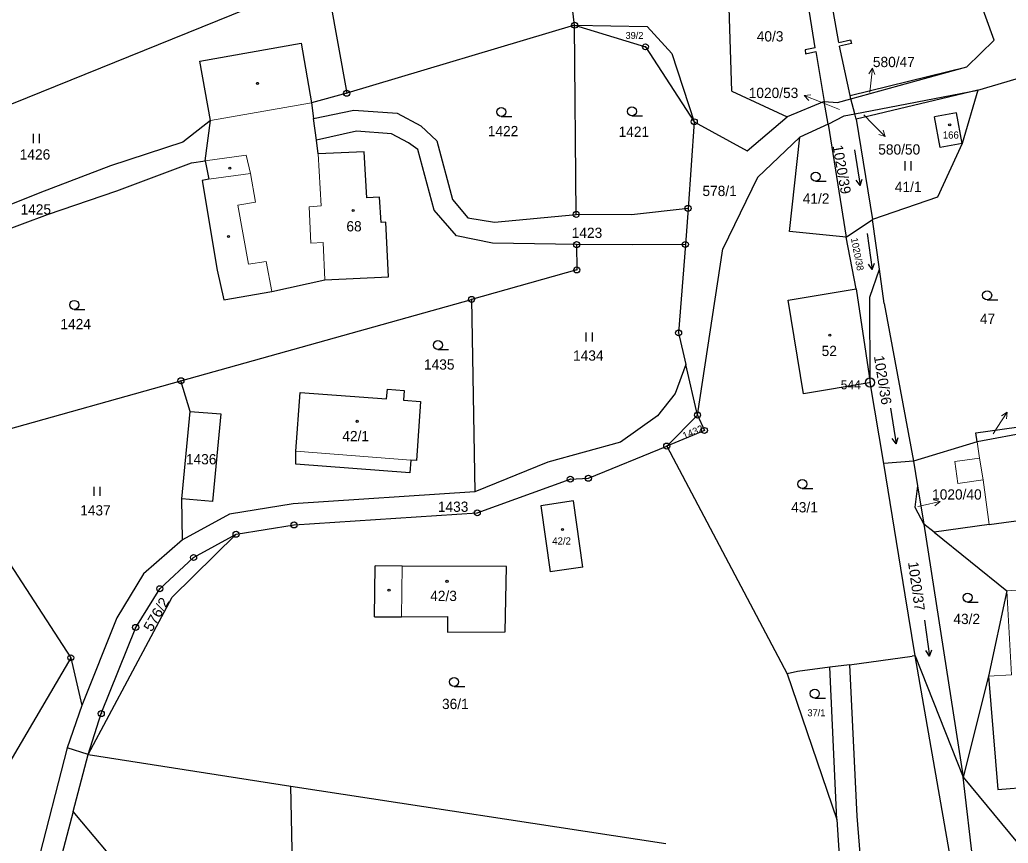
# Model space of a CAD drawing. Extents: x -601131 to -597152, y -1058536 to -1055911.
# Drawn here: x -599584.4 to -599420.5, y -1057414.9 to -1057278.4 of the extents above; entities that cross this region are included whole.
import ezdxf
from ezdxf.enums import TextEntityAlignment as Align

# ---------------------------------------------------------------- set-up
doc = ezdxf.new("R2010")
doc.units = 0
doc.header["$LTSCALE"] = 0.68
for name, color, linetype, lineweight in [('1', 7, 'Continuous', 25), ('3', 7, 'Continuous', 25), ('4', 7, 'Continuous', 13), ('5', 7, 'Continuous', 25), ('7', 7, 'Continuous', 13), ('8', 7, 'Continuous', 25)]:
    doc.layers.add(name, color=color, linetype=linetype, lineweight=lineweight)
doc.layers.add('2', color=7, linetype='Continuous')

msp = doc.modelspace()

# ---------------------------------------------------------------- linework, layer by layer
at = {"layer": '1'}
for p, q in [((-599492.41, -1057279.26), (-599496.24, -1057248.99)), ((-599452.51, -1057283), (-599457.48, -1057251.31)), ((-599448.59, -1057282.13), (-599454.14, -1057251.12)), ((-599422.85, -1057281.74), (-599428.69, -1057265.15)), ((-599533.67, -1057271.24), (-599655.03, -1057320.42)), ((-599533.67, -1057271.24), (-599530.2, -1057290.54)), ((-599466.34, -1057290.2), (-599466.89, -1057273.22)), ((-599492.41, -1057279.26), (-599530.2, -1057290.54)), ((-599492.41, -1057279.26), (-599480.38, -1057279.48)), ((-599492.41, -1057279.26), (-599480.65, -1057282.84)), ((-599492.14, -1057310.63), (-599492.41, -1057279.26)), ((-599480.38, -1057279.48), (-599476.29, -1057283.95)), ((-599554.56, -1057285.24), (-599537.77, -1057282.26)), ((-599537.77, -1057282.26), (-599536.01, -1057292.14)), ((-599480.65, -1057282.84), (-599472.56, -1057295.27)), ((-599448.59, -1057282.13), (-599446.63, -1057281.7)), ((-599446.48, -1057282.32), (-599448.47, -1057282.76)), ((-599446.73, -1057290.92), (-599448.47, -1057282.76)), ((-599446.63, -1057281.7), (-599446.48, -1057282.32)), ((-599427.36, -1057286.17), (-599422.85, -1057281.74)), ((-599476.29, -1057283.95), (-599472.56, -1057295.27)), ((-599452.51, -1057283), (-599454.18, -1057283.37)), ((-599454.18, -1057283.37), (-599454.13, -1057284.02)), ((-599454.13, -1057284.02), (-599452.39, -1057283.63)), ((-599452.39, -1057283.63), (-599451.02, -1057291.89)), ((-599552.77, -1057295.08), (-599554.56, -1057285.24)), ((-599446.73, -1057290.92), (-599427.36, -1057286.17)), ((-599446.59, -1057291.48), (-599427.36, -1057286.17)), ((-599425.53, -1057290.01), (-599413.41, -1057286.42)), ((-599530.2, -1057290.54), (-599536.01, -1057292.14)), ((-599466.34, -1057290.2), (-599457.17, -1057294.45)), ((-599446.59, -1057291.48), (-599446.73, -1057290.92)), ((-599445.96, -1057293.94), (-599425.53, -1057290.01)), ((-599425.53, -1057290.01), (-599445.73, -1057294.82)), ((-599425.53, -1057290.01), (-599428.11, -1057298.85)), ((-599536.01, -1057292.14), (-599535.68, -1057294.72)), ((-599451.02, -1057291.89), (-599457.17, -1057294.45)), ((-599451.02, -1057291.89), (-599448.79, -1057292.09)), ((-599450.38, -1057295.69), (-599451.02, -1057291.89)), ((-599448.79, -1057292.09), (-599446.59, -1057291.48)), ((-599445.96, -1057293.94), (-599446.59, -1057291.48)), ((-599535.68, -1057294.72), (-599529, -1057293.34)), ((-599529, -1057293.34), (-599521.84, -1057293.86)), ((-599521.84, -1057293.86), (-599517.91, -1057295.92)), ((-599463.81, -1057300.06), (-599457.17, -1057294.45)), ((-599450.38, -1057295.69), (-599447.7, -1057294.28)), ((-599447.7, -1057294.28), (-599445.96, -1057293.94)), ((-599445.73, -1057294.82), (-599445.96, -1057293.94)), ((-599429.07, -1057293.76), (-599432.75, -1057294.45)), ((-599431.79, -1057299.51), (-599432.75, -1057294.45)), ((-599428.11, -1057298.85), (-599429.07, -1057293.76)), ((-599552.77, -1057295.08), (-599557.36, -1057298.63)), ((-599553.64, -1057301.75), (-599552.77, -1057295.08)), ((-599535.22, -1057298.3), (-599535.68, -1057294.72)), ((-599517.91, -1057295.92), (-599515.24, -1057298.44)), ((-599472.56, -1057295.27), (-599473.6, -1057309.62)), ((-599472.56, -1057295.27), (-599463.81, -1057300.06)), ((-599450.38, -1057295.69), (-599455.08, -1057297.81)), ((-599450.38, -1057295.69), (-599447.39, -1057314.38)), ((-599445.73, -1057294.82), (-599442.98, -1057311.49)), ((-599528.55, -1057296.81), (-599535.22, -1057298.3)), ((-599522.75, -1057297.24), (-599528.55, -1057296.81)), ((-599519.95, -1057298.76), (-599522.75, -1057297.24)), ((-599557.36, -1057298.63), (-599569.37, -1057302.56)), ((-599534.92, -1057300.58), (-599535.22, -1057298.3)), ((-599518.42, -1057299.89), (-599519.95, -1057298.76)), ((-599515.24, -1057298.44), (-599512.64, -1057308.17)), ((-599462.09, -1057304.48), (-599455.08, -1057297.81)), ((-599456.78, -1057313.48), (-599455.08, -1057297.81)), ((-599428.11, -1057298.85), (-599432.25, -1057307.76)), ((-599428.11, -1057298.85), (-599431.79, -1057299.51)), ((-599527.3, -1057300.24), (-599534.92, -1057300.58)), ((-599526.87, -1057307.89), (-599527.3, -1057300.24)), ((-599515.68, -1057309.9), (-599518.42, -1057299.89)), ((-599569.37, -1057302.56), (-599581.09, -1057307.07)), ((-599568.34, -1057306.74), (-599555.93, -1057302.1)), ((-599555.93, -1057302.1), (-599553.64, -1057301.75)), ((-599553.64, -1057301.75), (-599553.04, -1057304.79)), ((-599553.04, -1057304.79), (-599554.18, -1057305.02)), ((-599554.18, -1057305.02), (-599551.67, -1057319.89)), ((-599462.09, -1057304.48), (-599467.85, -1057316.33)), ((-599581.09, -1057307.07), (-599593.17, -1057311.84)), ((-599579.79, -1057310.66), (-599568.34, -1057306.74)), ((-599524.73, -1057307.77), (-599526.87, -1057307.89)), ((-599524.5, -1057311.98), (-599524.73, -1057307.77)), ((-599512.64, -1057308.17), (-599510.12, -1057311.19)), ((-599432.25, -1057307.76), (-599442.98, -1057311.49)), ((-599591.79, -1057315.05), (-599579.79, -1057310.66)), ((-599512.01, -1057314.2), (-599515.68, -1057309.9)), ((-599505.68, -1057311.91), (-599492.14, -1057310.63)), ((-599482.98, -1057310.67), (-599492.14, -1057310.63)), ((-599473.6, -1057309.62), (-599482.98, -1057310.67)), ((-599473.6, -1057309.62), (-599474.03, -1057315.61)), ((-599523.7, -1057311.93), (-599524.5, -1057311.98)), ((-599523.26, -1057320.96), (-599523.7, -1057311.93)), ((-599510.12, -1057311.19), (-599505.68, -1057311.91)), ((-599447.39, -1057314.38), (-599442.98, -1057311.49)), ((-599441.85, -1057319.7), (-599442.98, -1057311.49)), ((-599447.39, -1057314.38), (-599456.78, -1057313.48)), ((-599506.01, -1057315.39), (-599512.01, -1057314.2)), ((-599492.08, -1057315.63), (-599506.01, -1057315.39)), ((-599482.76, -1057315.67), (-599492.08, -1057315.63)), ((-599492.08, -1057315.63), (-599492.04, -1057319.83)), ((-599474.03, -1057315.61), (-599482.76, -1057315.67)), ((-599474.03, -1057315.61), (-599475.16, -1057330.26)), ((-599445.72, -1057322.97), (-599447.39, -1057314.38)), ((-599472.02, -1057343.89), (-599467.85, -1057316.33)), ((-599551.67, -1057319.89), (-599550.59, -1057324.81)), ((-599492.04, -1057319.83), (-599509.5, -1057324.72)), ((-599443.43, -1057324.34), (-599441.85, -1057319.7)), ((-599441.06, -1057325.39), (-599441.85, -1057319.7)), ((-599542.62, -1057323.42), (-599533.81, -1057321.47)), ((-599533.81, -1057321.47), (-599523.26, -1057320.96)), ((-599550.59, -1057324.81), (-599542.62, -1057323.42)), ((-599456.99, -1057324.85), (-599445.72, -1057322.97)), ((-599445.72, -1057322.97), (-599443.39, -1057338.51)), ((-599557.68, -1057338.2), (-599509.5, -1057324.72)), ((-599509.5, -1057324.72), (-599508.95, -1057356.62)), ((-599454.46, -1057340.37), (-599456.99, -1057324.85)), ((-599443.39, -1057338.51), (-599443.43, -1057324.34)), ((-599441.06, -1057325.39), (-599436.21, -1057351.52)), ((-599475.16, -1057330.26), (-599473.95, -1057335.51)), ((-599473.95, -1057335.51), (-599475.75, -1057340.33)), ((-599472.02, -1057343.89), (-599473.95, -1057335.51)), ((-599598.4, -1057349.59), (-599557.68, -1057338.2)), ((-599556.17, -1057343.31), (-599557.68, -1057338.2)), ((-599443.56, -1057338.54), (-599454.46, -1057340.37)), ((-599443.39, -1057338.51), (-599443.56, -1057338.54)), ((-599441.15, -1057351.91), (-599443.39, -1057338.51)), ((-599538.63, -1057349.88), (-599537.94, -1057340.12)), ((-599537.94, -1057340.12), (-599523.57, -1057341.2)), ((-599523.57, -1057341.2), (-599523.44, -1057339.61)), ((-599523.44, -1057339.61), (-599520.65, -1057339.82)), ((-599520.65, -1057339.82), (-599520.75, -1057341.41)), ((-599475.75, -1057340.33), (-599478.67, -1057344.04)), ((-599520.75, -1057341.41), (-599517.95, -1057341.64)), ((-599517.95, -1057341.64), (-599518.61, -1057351.42)), ((-599557.53, -1057357.79), (-599556.17, -1057343.31)), ((-599556.17, -1057343.31), (-599551.09, -1057343.7)), ((-599551.09, -1057343.7), (-599552.47, -1057358.19)), ((-599478.67, -1057344.04), (-599484.82, -1057348.37)), ((-599477.13, -1057349.03), (-599472.02, -1057343.89)), ((-599472.02, -1057343.89), (-599470.88, -1057346.44)), ((-599425.85, -1057346.84), (-599409.99, -1057344.56)), ((-599470.88, -1057346.44), (-599477.13, -1057349.03)), ((-599425.64, -1057348.31), (-599425.85, -1057346.84)), ((-599409.88, -1057345.35), (-599425.64, -1057348.31)), ((-599484.82, -1057348.37), (-599496.86, -1057351.67)), ((-599425.64, -1057348.31), (-599436.21, -1057351.52)), ((-599598.4, -1057349.59), (-599575.95, -1057384.13)), ((-599538.61, -1057352.05), (-599538.63, -1057349.88)), ((-599490.11, -1057354.37), (-599477.13, -1057349.03)), ((-599477.13, -1057349.03), (-599457.16, -1057386.76)), ((-599519.54, -1057351.38), (-599519.7, -1057353.46)), ((-599518.61, -1057351.42), (-599519.54, -1057351.38)), ((-599496.86, -1057351.67), (-599508.95, -1057356.62)), ((-599436.21, -1057351.52), (-599441.15, -1057351.91)), ((-599436.21, -1057351.52), (-599435.55, -1057355.6)), ((-599519.7, -1057353.46), (-599538.61, -1057352.05)), ((-599437.59, -1057373.7), (-599441.15, -1057351.91)), ((-599508.55, -1057360.1), (-599493.12, -1057354.51)), ((-599493.12, -1057354.51), (-599490.11, -1057354.37)), ((-599508.95, -1057356.62), (-599539.06, -1057358.6)), ((-599435.55, -1057355.6), (-599435.98, -1057359.17)), ((-599435.55, -1057355.6), (-599434.51, -1057361.95)), ((-599552.47, -1057358.19), (-599557.53, -1057357.79)), ((-599557.45, -1057364.56), (-599557.53, -1057357.79)), ((-599492.6, -1057358.12), (-599497.98, -1057358.91)), ((-599491.02, -1057369.11), (-599492.6, -1057358.12)), ((-599539.06, -1057358.6), (-599549.61, -1057360.32)), ((-599497.98, -1057358.91), (-599496.44, -1057369.85)), ((-599435.98, -1057359.17), (-599434.51, -1057361.95)), ((-599423.64, -1057362.04), (-599397.5, -1057358.39)), ((-599549.61, -1057360.32), (-599557.45, -1057364.56)), ((-599538.92, -1057362.1), (-599508.55, -1057360.1)), ((-599548.54, -1057363.65), (-599538.92, -1057362.1)), ((-599432.8, -1057363.32), (-599434.51, -1057361.95)), ((-599434.51, -1057361.95), (-599427.99, -1057403.92)), ((-599423.64, -1057362.04), (-599432.8, -1057363.32)), ((-599557.45, -1057364.56), (-599563.87, -1057370.18)), ((-599559.12, -1057374.07), (-599548.54, -1057363.65)), ((-599555.58, -1057367.5), (-599548.54, -1057363.65)), ((-599432.8, -1057363.32), (-599420.72, -1057373.02)), ((-599561.19, -1057372.67), (-599555.58, -1057367.5)), ((-599525.6, -1057377.33), (-599525.47, -1057368.9)), ((-599520.98, -1057368.91), (-599525.47, -1057368.9)), ((-599503.67, -1057368.97), (-599520.98, -1057368.91)), ((-599503.9, -1057379.84), (-599503.67, -1057368.97)), ((-599491.02, -1057369.11), (-599496.44, -1057369.85)), ((-599563.87, -1057370.18), (-599568.3, -1057377.48)), ((-599565.19, -1057379.09), (-599561.19, -1057372.67)), ((-599420.72, -1057373.02), (-599423.75, -1057387.17)), ((-599573.06, -1057400.18), (-599559.12, -1057374.07)), ((-599435.94, -1057383.82), (-599437.59, -1057373.7)), ((-599568.3, -1057377.48), (-599574.13, -1057392.06)), ((-599525.6, -1057377.33), (-599521.1, -1057377.31)), ((-599521.1, -1057377.31), (-599513.5, -1057377.29)), ((-599513.5, -1057377.29), (-599513.49, -1057379.88)), ((-599570.89, -1057393.38), (-599565.19, -1057379.09)), ((-599513.49, -1057379.88), (-599503.9, -1057379.84)), ((-599575.95, -1057384.13), (-599608.22, -1057439.01)), ((-599575.95, -1057384.13), (-599574.13, -1057392.06)), ((-599446.83, -1057385.27), (-599436.42, -1057383.88)), ((-599435.94, -1057383.82), (-599436.42, -1057383.88)), ((-599435.94, -1057383.82), (-599427.99, -1057403.92)), ((-599429.13, -1057422.65), (-599435.94, -1057383.82)), ((-599450.07, -1057385.7), (-599455.47, -1057386.42)), ((-599446.83, -1057385.27), (-599450.07, -1057385.7)), ((-599448.9, -1057410.94), (-599450.07, -1057385.7)), ((-599446.83, -1057385.27), (-599445.63, -1057410.37)), ((-599455.47, -1057386.42), (-599457.16, -1057386.76)), ((-599457.16, -1057386.76), (-599448.9, -1057410.94)), ((-599423.75, -1057387.17), (-599427.99, -1057403.92)), ((-599423.75, -1057387.17), (-599422.24, -1057405.98)), ((-599574.13, -1057392.06), (-599576.56, -1057399.07)), ((-599573.06, -1057400.18), (-599570.89, -1057393.38)), ((-599576.56, -1057399.07), (-599582.83, -1057423.44)), ((-599573.06, -1057400.18), (-599576.56, -1057399.07)), ((-599575.56, -1057409.62), (-599573.06, -1057400.18)), ((-599573.06, -1057400.18), (-599539.45, -1057405.43)), ((-599427.99, -1057403.92), (-599418.95, -1057414.8)), ((-599425.81, -1057422.29), (-599427.99, -1057403.92)), ((-599539.45, -1057405.43), (-599477.25, -1057414.93)), ((-599538.83, -1057434.23), (-599539.45, -1057405.43)), ((-599422.24, -1057405.98), (-599409.22, -1057404.94)), ((-599575.56, -1057409.62), (-599579.52, -1057424.57)), ((-599574.11, -1057411.33), (-599575.56, -1057409.62)), ((-599445.63, -1057410.37), (-599444.9, -1057418.96)), ((-599553.62, -1057435.58), (-599574.11, -1057411.33)), ((-599448.9, -1057410.94), (-599448.41, -1057419.24))]:
    msp.add_line(p, q, dxfattribs=at)
at = {"layer": '3'}
for p, q in [((-599504.573, -1057294.38), (-599502.823, -1057294.38)), ((-599482.903, -1057294.3), (-599481.153, -1057294.3)), ((-599582.151, -1057298.79), (-599582.151, -1057297.29)), ((-599581.15, -1057298.79), (-599581.15, -1057297.29)), ((-599437.571, -1057303.32), (-599437.571, -1057301.82)), ((-599436.57, -1057303.32), (-599436.57, -1057301.82)), ((-599452.433, -1057305.11), (-599450.683, -1057305.11)), ((-599445.046, -1057305.831), (-599445.695, -1057304.945)), ((-599443.059, -1057319.749), (-599443.691, -1057318.851)), ((-599423.993, -1057324.79), (-599422.243, -1057324.79)), ((-599575.383, -1057326.37), (-599573.633, -1057326.37)), ((-599490.461, -1057331.69), (-599490.461, -1057330.19)), ((-599489.46, -1057331.69), (-599489.46, -1057330.19)), ((-599515.073, -1057333.04), (-599513.323, -1057333.04)), ((-599439.106, -1057348.651), (-599439.755, -1057347.765)), ((-599572.061, -1057357.3), (-599572.061, -1057355.8)), ((-599571.06, -1057357.3), (-599571.06, -1057355.8)), ((-599454.643, -1057356.07), (-599452.893, -1057356.07)), ((-599427.243, -1057374.89), (-599425.493, -1057374.89)), ((-599433.549, -1057383.839), (-599434.181, -1057382.941)), ((-599512.383, -1057388.87), (-599510.633, -1057388.87)), ((-599452.573, -1057390.81), (-599450.823, -1057390.81))]:
    msp.add_line(p, q, dxfattribs=at)
for points in [[(-599445.985, -1057299.905), (-599445.046, -1057305.831), (-599444.704, -1057304.788)], [(-599443.894, -1057313.807), (-599443.059, -1057319.749), (-599442.698, -1057318.712)], [(-599440.045, -1057342.725), (-599439.106, -1057348.651), (-599438.764, -1057347.608)], [(-599434.384, -1057377.897), (-599433.549, -1057383.839), (-599433.188, -1057382.802)]]:
    msp.add_lwpolyline(points, dxfattribs=at)
for centre in [(-599482.9029, -1057293.5498), (-599504.5729, -1057293.6298), (-599452.4329, -1057304.3598), (-599423.9929, -1057324.0398), (-599575.3829, -1057325.6198), (-599515.0729, -1057332.2898), (-599454.6429, -1057355.3198), (-599427.2429, -1057374.1398), (-599512.3829, -1057388.1198), (-599452.5729, -1057390.0598)]:
    msp.add_circle(centre, 0.75, dxfattribs=at)
at = {"layer": '4'}
for p, q in [((-599536.01, -1057292.14), (-599552.77, -1057295.08)), ((-599553.64, -1057301.75), (-599546.87, -1057300.79)), ((-599546.87, -1057300.79), (-599546.16, -1057303.85)), ((-599534.44, -1057309.22), (-599534.92, -1057300.58)), ((-599546.16, -1057303.85), (-599553.04, -1057304.79)), ((-599546.16, -1057303.85), (-599545.32, -1057308.61)), ((-599545.32, -1057308.61), (-599548.27, -1057309.12)), ((-599548.27, -1057309.12), (-599546.46, -1057318.89)), ((-599536.43, -1057309.38), (-599534.44, -1057309.22)), ((-599536.15, -1057315.38), (-599536.43, -1057309.38)), ((-599534.11, -1057315.28), (-599536.15, -1057315.38)), ((-599533.81, -1057321.47), (-599534.11, -1057315.28)), ((-599546.46, -1057318.89), (-599543.53, -1057318.44)), ((-599543.53, -1057318.44), (-599542.62, -1057323.42)), ((-599425.64, -1057348.31), (-599425.26, -1057351.03)), ((-599538.63, -1057349.88), (-599519.54, -1057351.38)), ((-599425.26, -1057351.03), (-599429.38, -1057351.61)), ((-599429.38, -1057351.61), (-599428.87, -1057355.23)), ((-599424.65, -1057354.65), (-599425.26, -1057351.03)), ((-599428.87, -1057355.23), (-599424.65, -1057354.65)), ((-599424.65, -1057354.65), (-599423.64, -1057362.04)), ((-599520.98, -1057368.91), (-599521.1, -1057377.31)), ((-599420.72, -1057373.02), (-599411.3, -1057372.3)), ((-599420.72, -1057373.02), (-599419.97, -1057386.97)), ((-599419.97, -1057386.97), (-599423.75, -1057387.17))]:
    msp.add_line(p, q, dxfattribs=at)
at = {"layer": '5'}
for centre in [(-599544.9768, -1057288.9092), (-599430.2068, -1057295.7892), (-599549.5868, -1057302.9592), (-599529.1268, -1057309.9792), (-599549.7868, -1057314.2992), (-599450.0668, -1057330.6292), (-599528.4468, -1057344.9192), (-599494.4068, -1057362.8492), (-599513.5568, -1057371.4592), (-599523.1768, -1057372.9292)]:
    msp.add_circle(centre, 0.175, dxfattribs=at)
at = {"layer": '7'}
for p, q in [((-599443.016, -1057286.365), (-599443.619, -1057287.309)), ((-599454.322, -1057290.935), (-599453.566, -1057291.761)), ((-599440.898, -1057297.712), (-599441.252, -1057296.65)), ((-599420.676, -1057343.423), (-599421.641, -1057343.99)), ((-599431.796, -1057358.195), (-599432.884, -1057357.932))]:
    msp.add_line(p, q, dxfattribs=at)
for points in [[(-599443.44, -1057290.39), (-599443.33, -1057289.35), (-599443.016, -1057286.365), (-599442.623, -1057287.414)], [(-599448.47, -1057293.21), (-599451.52, -1057292.01), (-599454.322, -1057290.935), (-599453.207, -1057290.826)], [(-599444.46, -1057294.13), (-599443.02, -1057295.59), (-599440.898, -1057297.712), (-599441.96, -1057297.358)], [(-599422.99, -1057346.99), (-599422.31, -1057345.94), (-599420.676, -1057343.423), (-599420.801, -1057344.536)], [(-599435.47, -1057359.04), (-599434.72, -1057358.87), (-599431.796, -1057358.195), (-599432.659, -1057358.908)]]:
    msp.add_lwpolyline(points, dxfattribs=at)
at = {"layer": '8'}
for centre, radius in [((-599492.41, -1057279.2599), 0.5), ((-599492.41, -1057279.2599), 0.0303), ((-599480.65, -1057282.8399), 0.5), ((-599480.65, -1057282.8399), 0.0303), ((-599530.2, -1057290.5399), 0.5), ((-599530.2, -1057290.5399), 0.0303), ((-599472.56, -1057295.2699), 0.5), ((-599472.56, -1057295.2699), 0.0303), ((-599473.6, -1057309.6199), 0.5), ((-599492.14, -1057310.6299), 0.5), ((-599492.14, -1057310.6299), 0.0303), ((-599473.6, -1057309.6199), 0.0303), ((-599492.08, -1057315.6299), 0.5), ((-599492.08, -1057315.6299), 0.0303), ((-599474.03, -1057315.6099), 0.5), ((-599474.03, -1057315.6099), 0.0303), ((-599492.04, -1057319.8299), 0.5), ((-599492.04, -1057319.8299), 0.0303), ((-599509.5, -1057324.7199), 0.5), ((-599509.5, -1057324.7199), 0.0303), ((-599475.16, -1057330.2599), 0.5), ((-599475.16, -1057330.2599), 0.0303), ((-599557.68, -1057338.1999), 0.5), ((-599557.68, -1057338.1999), 0.0303), ((-599443.43, -1057338.4898), 0.75), ((-599443.43, -1057338.4898), 0.03), ((-599472.02, -1057343.8899), 0.5), ((-599472.02, -1057343.8899), 0.0303), ((-599470.88, -1057346.4399), 0.5), ((-599470.88, -1057346.4399), 0.0303), ((-599477.13, -1057349.0299), 0.5), ((-599477.13, -1057349.0299), 0.0303), ((-599493.12, -1057354.5099), 0.5), ((-599493.12, -1057354.5099), 0.0303), ((-599490.11, -1057354.3699), 0.5), ((-599490.11, -1057354.3699), 0.0303), ((-599508.55, -1057360.0999), 0.5), ((-599538.92, -1057362.0999), 0.5), ((-599508.55, -1057360.0999), 0.0303), ((-599548.54, -1057363.6499), 0.5), ((-599538.92, -1057362.0999), 0.0303), ((-599548.54, -1057363.6499), 0.0303), ((-599555.58, -1057367.4999), 0.5), ((-599555.58, -1057367.4999), 0.0303), ((-599561.19, -1057372.6699), 0.5), ((-599561.19, -1057372.6699), 0.0303), ((-599565.19, -1057379.0899), 0.5), ((-599565.19, -1057379.0899), 0.0303), ((-599575.95, -1057384.1299), 0.5), ((-599575.95, -1057384.1299), 0.0303), ((-599570.89, -1057393.3799), 0.5), ((-599570.89, -1057393.3799), 0.0303)]:
    msp.add_circle(centre, radius, dxfattribs=at)

# ---------------------------------------------------------------- texts
at = {"layer": '2'}
for s, height, p in [('39/2', 1.14, (-599483.96, -1057281.525)), ('40/3', 1.7, (-599462.2, -1057281.955)), ('580/47', 1.7, (-599442.94, -1057286.205)), ('166', 1.19, (-599431.35, -1057298.057)), ('580/50', 1.7, (-599442.05, -1057300.705)), ('578/1', 1.7, (-599471.2, -1057307.584)), ('41/1', 1.7, (-599439.3, -1057306.905)), ('41/2', 1.7, (-599454.57, -1057308.844)), ('47', 1.7, (-599425.19, -1057328.785)), ('52', 1.7, (-599451.44, -1057334.104)), ('1020/40', 1.7, (-599433.12, -1057357.895)), ('43/1', 1.7, (-599456.49, -1057360.025)), ('42/2', 1.19, (-599496.11, -1057365.347)), ('42/3', 1.7, (-599516.35, -1057374.715)), ('43/2', 1.7, (-599429.59, -1057378.535)), ('36/1', 1.7, (-599514.39, -1057392.625)), ('37/1', 1.14, (-599453.79, -1057393.815))]:
    msp.add_text(s, height=height, dxfattribs=at).set_placement(p)
msp.add_text('1020/53', height=1.7, dxfattribs=at).set_placement((-599455.31, -1057291.334), align=Align.RIGHT)
for s, p in [('1422', (-599504.27, -1057297.662)), ('1421', (-599482.58, -1057297.772)), ('1426', (-599581.88, -1057301.532)), ('1425', (-599581.75, -1057310.642)), ('68', (-599528.979, -1057313.442)), ('1423', (-599490.35, -1057314.522)), ('1424', (-599575.14, -1057329.652)), ('1434', (-599490.13, -1057334.872)), ('1435', (-599514.85, -1057336.352)), ('42/1', (-599528.709, -1057348.222)), ('1436', (-599554.33, -1057352.062)), ('1433', (-599512.55, -1057359.932)), ('1437', (-599571.86, -1057360.532))]:
    msp.add_text(s, height=1.7, dxfattribs=at).set_placement(p, align=Align.CENTER)
for s, height, rotation, p in [('1020/39', 1.7, 280, (-599449.638, -1057299.273)), ('1020/38', 1.14, 281, (-599446.589, -1057314.624)), ('1020/36', 1.7, 279, (-599442.779, -1057334.156)), ('1020/37', 1.7, 278, (-599437.12, -1057368.309))]:
    msp.add_text(s, height=height, rotation=rotation, dxfattribs=at).set_placement(p)
at = {"layer": '2', "width": 1.05}
msp.add_text('1432', height=1.139, rotation=23, dxfattribs=at).set_placement((-599472.5805, -1057347.2328), align=Align.CENTER)
msp.add_text('576/2', height=1.7, rotation=60, dxfattribs=at).set_placement((-599562.531, -1057379.932))
at = {"layer": '8'}
msp.add_text('544', height=1.5, dxfattribs=at).set_placement((-599444.929, -1057339.607), align=Align.RIGHT)

doc.saveas('drawing.dxf')
